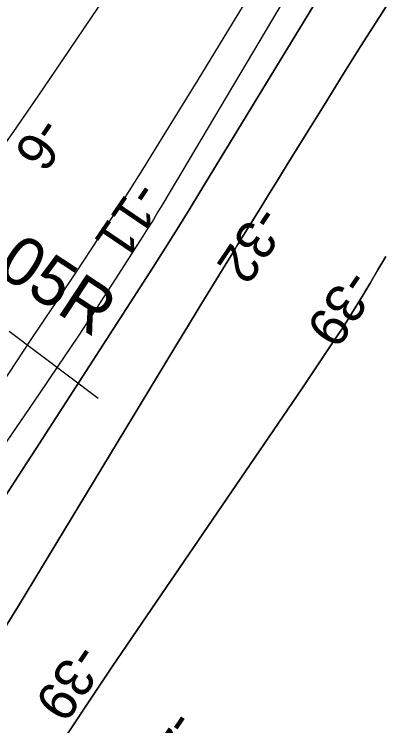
# Model space of a CAD drawing. Extents: x 3905714 to 3926767, y 183354 to 205755.
# Drawn here: x 3915848 to 3916162, y 192631 to 193245 of the extents above; entities that cross this region are included whole.
import ezdxf

# ---------------------------------------------------------------- set-up
doc = ezdxf.new("R2010")
doc.units = 0
for name, color, linetype in [('V-LEVE-TOET', 7, 'Continuous'), ('V-RIVR-RANG', 7, 'Continuous'), ('V-STRM-FMON', 7, 'Continuous'), ('V-TOPO-DPTH', 7, 'Continuous'), ('V-TOPO-MINR', 7, 'Continuous')]:
    doc.layers.add(name, color=color, linetype=linetype)

msp = doc.modelspace()

# ---------------------------------------------------------------- linework, layer by layer
at = {"layer": 'V-LEVE-TOET'}
msp.add_line((3915920.03, 192913.74), (3915843.24, 192971.46), dxfattribs=at)
at = {"layer": 'V-TOPO-DPTH'}
for points in [[(3915839.21, 192715.42), (3915851.19, 192734.94), (3915976.76, 192942.35), (3915986.79, 192958.89), (3915996.84, 192975.42), (3916006.92, 192991.93), (3916017.01, 193008.43), (3916031.59, 193032.21), (3916034.41, 193036.81), (3916037.24, 193041.41), (3916040.06, 193046), (3916042.89, 193050.59), (3916052.39, 193066.01), (3916059.97, 193078.31), (3916067.55, 193090.61), (3916075.14, 193102.91), (3916082.72, 193115.2), (3916098.78, 193141.25), (3916114.44, 193166.54), (3916130.16, 193191.79), (3916145.98, 193216.98), (3916161.87, 193242.13), (3916428.73, 193662.94)], [(3915839.21, 192715.42), (3915851.19, 192734.94), (3915976.76, 192942.35), (3915986.79, 192958.89), (3915996.84, 192975.42), (3916006.92, 192991.93), (3916017.01, 193008.43), (3916031.59, 193032.21), (3916034.41, 193036.81), (3916037.24, 193041.41), (3916040.06, 193046), (3916042.89, 193050.59), (3916052.39, 193066.01), (3916059.97, 193078.31), (3916067.55, 193090.61), (3916075.14, 193102.91), (3916082.72, 193115.2), (3916098.78, 193141.25), (3916114.44, 193166.54), (3916130.16, 193191.79), (3916145.98, 193216.98), (3916161.87, 193242.13), (3916428.73, 193662.94)], [(3916071.24, 193295.95), (3916038.6, 193242.12), (3916005.79, 193188.39), (3915976.61, 193140.86), (3915958.09, 193111.09), (3915939.35, 193081.45), (3915920.28, 193052.03), (3915900.98, 193022.75), (3915881.52, 192993.58), (3915862.05, 192964.41), (3915842.58, 192935.24), (3915823.11, 192906.08), (3915766.82, 192821.76), (3915746.12, 192790.6), (3915725.5, 192759.39), (3915705.02, 192728.08), (3915684.62, 192696.72), (3915328.37, 192146.33)], [(3915354.77, 192101.61), (3915594.9, 192461.92), (3915624.41, 192506.19), (3915653.92, 192550.47), (3915683.44, 192594.74), (3915712.95, 192639.01), (3915761.89, 192712.4), (3915766.95, 192719.97), (3915772, 192727.54), (3915777.07, 192735.1), (3915782.14, 192742.65), (3915803.87, 192774.99), (3915819.73, 192798.77), (3915835.5, 192822.6), (3915851.13, 192846.53), (3915866.67, 192870.51), (3915967.26, 193026.84), (3915977.72, 193043.23), (3915988.09, 193059.68), (3915998.32, 193076.2), (3916008.47, 193092.79), (3916079.15, 193209.31), (3916124.67, 193284.13)], [(3916124.67, 193284.13), (3916079.15, 193209.31), (3916008.47, 193092.79), (3915998.32, 193076.2), (3915988.09, 193059.68), (3915977.72, 193043.23), (3915967.26, 193026.84), (3915866.67, 192870.51), (3915851.13, 192846.53), (3915835.5, 192822.6), (3915819.73, 192798.77), (3915803.87, 192774.99), (3915782.14, 192742.65), (3915777.07, 192735.1), (3915772, 192727.54), (3915766.95, 192719.97), (3915761.89, 192712.4), (3915712.95, 192639.01), (3915683.44, 192594.74), (3915653.92, 192550.47), (3915624.41, 192506.19), (3915594.9, 192461.92), (3915354.77, 192101.61)], [(3916167.64, 193036.04), (3916160.91, 193024.49), (3916154.09, 193013), (3916147.2, 193001.55), (3916138.4, 192987.04), (3916135.84, 192982.89), (3916133.25, 192978.76), (3916130.6, 192974.66), (3916127.92, 192970.59), (3916120.7, 192959.78), (3916114.37, 192950.33), (3916108.02, 192940.89), (3916101.65, 192931.47), (3916095.25, 192922.06), (3915953.91, 192714.59), (3915931.82, 192681.92), (3915909.88, 192649.15), (3915888.18, 192616.22)], [(3915888.18, 192616.22), (3915909.88, 192649.15), (3915931.82, 192681.92), (3915953.91, 192714.59), (3916095.25, 192922.06), (3916101.65, 192931.47), (3916108.02, 192940.89), (3916114.37, 192950.33), (3916120.7, 192959.78), (3916127.92, 192970.59), (3916130.6, 192974.66), (3916133.25, 192978.76), (3916135.84, 192982.89), (3916138.4, 192987.04), (3916147.2, 193001.55), (3916154.09, 193013), (3916160.91, 193024.49), (3916167.64, 193036.04)]]:
    msp.add_lwpolyline(points, dxfattribs=at)
at = {"layer": 'V-TOPO-MINR'}
for points in [[(3916302.39, 193862.02), (3916291.68, 193845.05), (3916280.12, 193826.48), (3916268.58, 193807.89), (3916257.09, 193789.28), (3916245.62, 193770.65), (3916060.21, 193468.76), (3916025.95, 193413.77), (3915991.21, 193359.08), (3915955.78, 193304.84), (3915919.87, 193250.9), (3915888.75, 193204.81), (3915867.92, 193174.24), (3915846.9, 193143.8), (3915825.61, 193113.55), (3915804.14, 193083.42), (3915621.99, 192830.25), (3915621.99, 192830.25)], [(3916428.73, 193662.94), (3916161.87, 193242.13), (3916145.98, 193216.98), (3916130.16, 193191.79), (3916114.44, 193166.54), (3916098.78, 193141.25), (3916082.72, 193115.2), (3916075.14, 193102.91), (3916067.55, 193090.61), (3916059.97, 193078.31), (3916052.39, 193066.01), (3916042.89, 193050.59), (3916040.06, 193046), (3916037.24, 193041.41), (3916034.41, 193036.81), (3916031.59, 193032.21), (3916017.01, 193008.43), (3916006.92, 192991.93), (3915996.84, 192975.42), (3915986.79, 192958.89), (3915976.76, 192942.35), (3915851.19, 192734.94), (3915839.21, 192715.42)], [(3916152.77, 193380.41), (3915975.7, 193081.51), (3915971.46, 193074.44), (3915967.17, 193067.4), (3915962.8, 193060.41), (3915958.39, 193053.45), (3915934.83, 193016.79), (3915918.49, 192991.6), (3915902, 192966.51), (3915885.28, 192941.57), (3915868.41, 192916.72), (3915775.16, 192780.66), (3915762.32, 192761.81), (3915749.55, 192742.92), (3915736.88, 192723.95), (3915724.29, 192704.93), (3915558.62, 192453.25), (3915516.92, 192389.85)], [(3916071.24, 193295.95), (3916038.6, 193242.12), (3916005.79, 193188.39), (3915976.61, 193140.86), (3915958.09, 193111.09), (3915939.35, 193081.45), (3915920.28, 193052.03), (3915900.98, 193022.75), (3915881.52, 192993.58), (3915862.05, 192964.41), (3915842.58, 192935.24), (3915823.11, 192906.08), (3915766.82, 192821.76), (3915746.12, 192790.6), (3915725.5, 192759.39), (3915705.02, 192728.08), (3915684.62, 192696.72), (3915328.37, 192146.33)], [(3916124.67, 193284.13), (3916079.15, 193209.31), (3916008.47, 193092.79), (3915998.32, 193076.2), (3915988.09, 193059.68), (3915977.72, 193043.23), (3915967.26, 193026.84), (3915866.67, 192870.51), (3915851.13, 192846.53), (3915835.5, 192822.6), (3915819.73, 192798.77), (3915803.87, 192774.99), (3915782.14, 192742.65), (3915777.07, 192735.1), (3915772, 192727.54), (3915766.95, 192719.97), (3915761.89, 192712.4), (3915712.95, 192639.01), (3915683.44, 192594.74), (3915653.92, 192550.47), (3915624.41, 192506.19), (3915594.9, 192461.92), (3915354.77, 192101.61)], [(3916167.64, 193036.04), (3916160.91, 193024.49), (3916154.09, 193013), (3916147.2, 193001.55), (3916138.4, 192987.04), (3916135.84, 192982.89), (3916133.25, 192978.76), (3916130.6, 192974.66), (3916127.92, 192970.59), (3916120.7, 192959.78), (3916114.37, 192950.33), (3916108.02, 192940.89), (3916101.65, 192931.47), (3916095.25, 192922.06), (3915953.91, 192714.59), (3915931.82, 192681.92), (3915909.88, 192649.15), (3915888.18, 192616.22)]]:
    msp.add_lwpolyline(points, dxfattribs=at)

# ---------------------------------------------------------------- texts
at = {"layer": 'V-RIVR-RANG'}
for s, rotation, p in [('-6', 235.87833, (3915868.89, 193158.76)), ('-11', 235.87833, (3915952.18, 193103.41)), ('-32', 236.01567, (3916057.13, 193082.13)), ('-39', 236.01567, (3916134.25, 193027.49)), ('-39', 235.60042, (3915900.83, 192704.86)), ('-45', 235.60042, (3915983.38, 192647.35))]:
    msp.add_text(s, height=33.5, rotation=rotation, dxfattribs=at).set_placement(p)
at = {"layer": 'V-STRM-FMON'}
msp.add_text('11.05R', height=42, rotation=326.66461, dxfattribs=at).set_placement((3915765.49, 193065.4))

doc.saveas('drawing.dxf')
